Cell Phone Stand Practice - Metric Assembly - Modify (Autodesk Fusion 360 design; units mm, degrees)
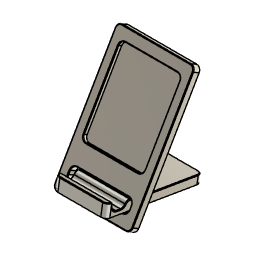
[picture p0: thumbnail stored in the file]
sketch "Main Body Sketch" plane through (0, 0, 0) normal (0, 1, 0) x axis (1, 0, 0)
  line L1 (30, 0) -> (-30, 0)
  line L2 (30, -100) -> (30, 0)
  line L3 (-30, -100) -> (30, -100)
  line L4 (-30, 0) -> (-30, -100)
  line L5 (30, -100) -> (-30, 0)
  line L6 (-30, -100) -> (30, 0)
  line L7 (23.5, -17.5) -> (-23.5, -17.5)
  line L8 (23.5, -8) -> (23.5, -17.5)
  line L9 (-23.5, -8) -> (23.5, -8)
  line L10 (-23.5, -17.5) -> (-23.5, -8)
  line L11 (0, 0) -> (0, -8)
  line L12 (23.5, -92) -> (-23.5, -92)
  line L13 (23.5, -32) -> (23.5, -92)
  line L14 (-23.5, -32) -> (23.5, -32)
  line L15 (-23.5, -92) -> (-23.5, -32)
  line L16 (0, -62.5) -> (0, -50)
  line L17 (17.2022, -62.0451) -> (0, -50)
  line L18 (21, -50) -> (0, -50)
  line L19 (17.2022, -37.9549) -> (0, -50)
  circle C1 centre (0, -50) radius 12.5
  point P6 (0, -50)
  point P1 (0, 0)
  point P11 (0, -8)
  point P12 (0, 0)
  point P17 (0, -50)
  point P21 (0, -50)
  point P22 (0, -62.5)
  point P18 (17.2022, -62.0451)
  point P23 (17.2022, -62.0451)
  point P19 (21, -50)
  point P24 (21, -50)
  point P25 (0, -50)
  point P20 (17.2022, -37.9549)
  point P26 (17.2022, -37.9549)
  point P27 (-17.2022, -62.0451)
  point P28 (-21, -50)
  point P29 (-17.2022, -37.9549)
  point P30 (0, -25)
  point P4 (30, -100)
  point P5 (-30, -100)
  point P3 (30, 0)
  point P8 (23.5, -17.5)
  point P9 (23.5, -8)
  point P7 (-23.5, -17.5)
  point P14 (23.5, -92)
  point P15 (23.5, -32)
  horizontal L1
  perpendicular L1 L2
  parallel L1 L3
  parallel L2 L4
  coincident L5 P6
  coincident L6 P6
  midpoint P1 L1
  horizontal L7
  vertical L8
  horizontal L9
  vertical L10
  midpoint L9 P11
  coincident P1 P12
  vertical L11
  horizontal L12
  vertical L13
  horizontal L14
  vertical L15
  collinear L8 L13
  collinear L10 L15
  coincident P6 P17
  coincident P6 P21
  coincident C1 P22
  vertical L16
  coincident P18 P23
  coincident P19 P24
  perpendicular L16 L18
  coincident P17 P25
  coincident P20 P26
  equal L17 L18
  equal L18 L19
  symmetric P18 L16 P27
  symmetric P19 L16 P28
  symmetric P20 L16 P29
  vertical P6 P30
  dimension "d1" distance P4 P5 = 60
  dimension "d2" distance P3 P4 = 100
  dimension "d3" distance P8 P9 = 9.5
  dimension "d4" distance L1 L9 = 8
  dimension "d5" distance P7 P8 = 47
  dimension "d6" distance L3 L12 = 8 (= "d4")
  dimension "d7" distance P14 P15 = 60
  dimension "d8" diameter C1 = 25
  dimension "d9" distance P21 P24 = 21
  dimension "d10" angle L17 L18 = 35
  dimension "d11" angle L18 L19 = 35 (= "d10")
  dimension "d12" distance P17 P30 = 25
  dimension "d15" R-Pattern1-uDistance = 21
  dimension "d16" R-Pattern1-vDistance = 0
extrude "Extrude1" new body sketch "Main Body Sketch" profile of L1 L2 L3 L4 L7 L8 L9 L10 L12 L13 L14 L15 C1 along normal blind 5.5
extrude "Extrude2" cut sketch "Main Body Sketch" profile of L12 L13 L14 L15 C1 along normal blind 3
fillet "Fillet1" radius 3.5
chamfer "Chamfer1" distance 0.5
move "Move1"
sketch "Stand Body Sketch" plane through (0, 0, 0) normal (1, 0, 0) x axis (0, 1, 0)
  line L1 (14.7999, 15.9408) -> (10.4698, 18.4408)
  line L2 (5.7198, 10.2135) -> (10.0499, 7.7135)
  line L3 (66.5456, 2.9579) -> (12.5794, 12.0948)
  line L4 (66.0448, 0) -> (66.5456, 2.9579)
  line L5 (-7.9029, 12.52) -> (66.0448, 0)
  line L6 (-6.317, 21.8867) -> (-7.9029, 12.52)
  line L7 (-2.3731, 21.2189) -> (-6.317, 21.8867)
  line L8 (-2.3281, 14.6188) -> (-2.3731, 21.2189)
  line L9 (6.5456, 13.1164) -> (-2.3281, 14.6188)
  line L10 (8.7802, 17.0486) -> (6.5456, 13.1164)
  line L11 (16.0467, 18.1003) -> (19.9906, 17.4326)
  line L12 (24.2831, 10.1133) -> (19.9906, 17.4326)
  line L13 (16.0467, 18.1003) -> (12.5794, 12.0948)
  line L14 (54.2999, 84.3568) -> (7.7999, 3.8164)
  line L15 (13.6992, 16.2157) -> (8.7802, 17.0486)
  line L16 (12.1028, 18.768) -> (11.7272, 16.5496)
  line L17 (16.0467, 18.1003) -> (12.1028, 18.768)
  line L18 (15.6711, 15.8819) -> (16.0467, 18.1003)
  line L19 (67.0881, 6.1623) -> (22.1368, 13.7729)
  line L20 (66.5456, 2.9579) -> (67.0881, 6.1623)
  circle C1 centre (13.6992, 16.2157) radius 2
  point P17 (24.2831, 10.1133)
  point P16 (16.0467, 18.1003)
  point P1 (0, 0)
  point P8 (66.0448, 0)
  point P18 (16.0467, 18.1003)
  point P5 (5.7198, 10.2135)
  point P23 (11.7272, 16.5496)
  point P26 (15.6711, 15.8819)
  point P21 (13.6992, 16.2157)
  point P22 (13.6992, 16.2157)
  point P25 (16.0467, 18.1003)
  point P28 (22.1368, 13.7729)
  point P30 (66.5456, 2.9579)
  point P7 (66.5456, 2.9579)
  point P9 (-7.9029, 12.52)
  point P10 (-6.317, 21.8867)
  point P11 (-2.3731, 21.2189)
  point P12 (-2.3281, 14.6188)
  point P13 (6.5456, 13.1164)
  point P15 (19.9906, 17.4326)
  point P14 (8.7802, 17.0486)
  point P27 (6.0499, 0.7853)
  perpendicular L3 L4
  perpendicular L5 L6
  perpendicular L6 L7
  parallel L3 L9
  coincident L3 P17
  collinear L7 L11
  perpendicular L1 L13
  coincident P16 L13
  parallel L3 L5
  horizontal P1 P8
  collinear L3 L9
  coincident P16 P18
  collinear L13 L14
  coincident P5 L5
  parallel L5 L15
  coincident C1 P23
  perpendicular L16 L17
  coincident C1 P26
  tangent C1 L18
  perpendicular L17 L18
  tangent C1 L16
  parallel L6 L16
  coincident P21 P22
  collinear L11 L17
  coincident P18 P25
  midpoint L12 P28
  perpendicular L4 L19
  coincident L3 P30
  perpendicular L3 L20
  coincident P7 P30
  dimension "d30" distance P8 P9 = 75
  dimension "d31" distance P7 P8 = 3
  dimension "d32" distance P9 P10 = 9.5
  dimension "d33" angle L11 L12 = 50
  dimension "d34" distance P10 P11 = 4
  dimension "d35" distance P12 P13 = 9
  dimension "d36" distance P15 P16 = 4
  dimension "d37" distance L9 P14 = 4.25
  dimension "d38" angle L9 L10 = 70
  dimension "d39" angle L8 L9 = 100
  dimension "d40" diameter C1 = 4
  dimension "d41" distance P8 P27 = 60
extrude "Extrude3" new body sketch "Stand Body Sketch" profile of L3 L4 L5 L6 L7 L8 L9 L10 L11 L12 L13 L14 L15 C1 L18 L19 L20 distance 40
fillet "Fillet2" radius 3.5
chamfer "Chamfer2" distance 0.5
named bodies: "Main Body", "Stand Body"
